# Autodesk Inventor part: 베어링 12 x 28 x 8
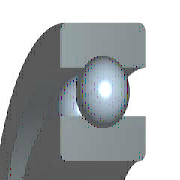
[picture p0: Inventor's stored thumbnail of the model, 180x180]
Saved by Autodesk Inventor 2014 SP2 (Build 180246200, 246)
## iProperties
IsCustomPart: 1
Created: 2012-02
Part Number: 베어링 12 x 28 x 8
Material: 강철, 연강
Description: 깊은 그루브 볼 베어링
Document SubType Name: Modeling
Standard: KS B 2023
Designer: mduedu
Standards Organization: KS
Language: ko-KR
Size Designation: 6001 - 12 x 28 x 8
Categories: <MemberInstance><Categories><Category DisplayName="샤프트 부품" InternalName="7f7aeb1f-a693-4053-b835-cee3144e0d98" Mnemonic="SHFT"><Category DisplayName="베어링" Inter
Density: 7.86 g/cm^3
Appearance: 노란색
Mass: 21.4854 g
Surface Area: 31.1809 cm^2
Volume: 2.73351 cm^3
Author: mduedu
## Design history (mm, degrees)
sketch "스케치" dims "d0" = 4.16 (= -0.26 x WD + 0.26 x BD)
  geometry: L1 (1.92, 10)-(6.08, 10); L2 (4, 10)-(4, 7.92); L3 (4, 10)-(4, 12.08); L4 (2.454, 8.608)-(0, 8.608); L5 (0, 6)-(8, 6); L6 (2.454, 11.392)-(0, 11.392); L7 (0, 14)-(8, 14); L8 (8, 6)-(8, 8.608); L9 (5.546, 8.608)-(8, 8.608); L10 (5.546, 11.392)-(8, 11.392); L11 (8, 14)-(8, 11.392); L12 (-1.4, 0)-(8.4, 0) reference; L13 (0, -0.3)-(0, 5.3) reference
  constraints: 22 end point, 4 point on line, 2 collinear, 2 perpendicular, 2 symmetric about line, 1 midpoint, 1 parallel, 14 other
  dimensions: "d9" = 12 diameter of L5 L12 (= WD); "d11" = 28 diameter of L7 L12 (= BD); "d12" = 8 distance between parallel lines of L8 L13 (= KB); "d13" = 17.216 diameter of L9 L12 (= 0.326 x BD + 0.674 x WD)
revolve "본체" stored, may be unused: angle "d6" = 90 deg
revolve "볼" stored, may be unused: angle "d7" = 90 deg
pattern_circular "IDS_ARRAYBALL[SIMPL:T]" dims angle "d3" = 360 deg
body "Solid1"
fillet "모깎기1" dims "d1" = 0.3 (= KRS)
other parameters: "WD" = 12 [user parameter; used in 5 equation terms], "BD" = 28 [user parameter; used in 5 equation terms], "KB" = 8 [user parameter; used in 1 equation term], "KRS" = 0.3 [user parameter; used in 1 equation term], "d4" = 0, "d5" = 0, "d8" = 0, "d14" = 0, "d15" = 0, "BBA" = 0 [user parameter], "BC0" = 2360000 [user parameter], "BC" = 5070000 [user parameter], "BR" = 14 (= 0.5 x BD) [user parameter], "WR" = 6 (= 0.5 x WD) [user parameter]
